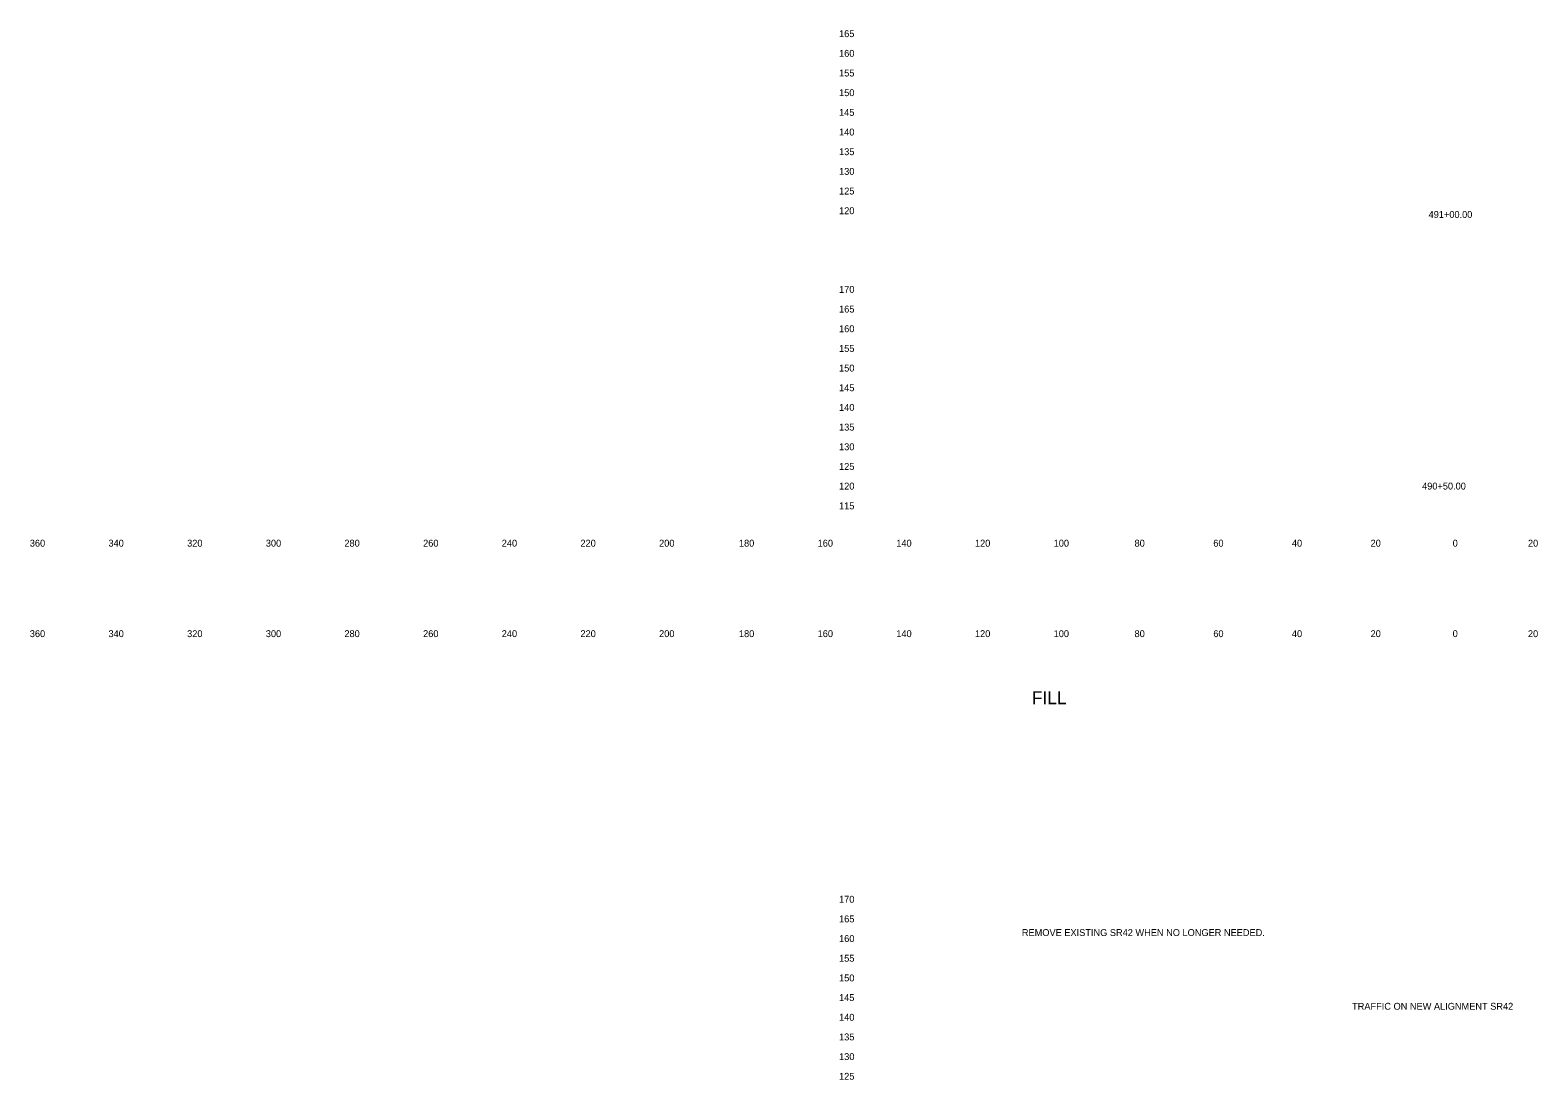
# Model space of a CAD drawing. Extents: x 21281 to 22024, y 6472 to 15208.
# Drawn here: x 21280.5 to 21663.8, y 14389.8 to 14656.6 of the extents above; entities that cross this region are included whole.
import ezdxf

# ---------------------------------------------------------------- set-up
doc = ezdxf.new("R2010")
doc.units = 0
for name, color, linetype in [('XS_SHEET_LABELS_ELEVATION', 7, 'Continuous'), ('XS_SHEET_LABELS_OFFSET', 7, 'Continuous'), ('XS_SHEET_LABELS_STATION', 7, 'Continuous')]:
    doc.layers.add(name, color=color, linetype=linetype)

msp = doc.modelspace()

# ---------------------------------------------------------------- texts
at = {"layer": 'XS_SHEET_LABELS_ELEVATION'}
for s, p in [('  165  ', (21484.84, 14654.84)), ('  160  ', (21484.84, 14649.84)), ('  155  ', (21484.84, 14644.84)), ('  150  ', (21484.84, 14639.84)), ('  145  ', (21484.84, 14634.84)), ('  140  ', (21484.84, 14629.84)), ('  135  ', (21484.84, 14624.84)), ('  130  ', (21484.84, 14619.84)), ('  125  ', (21484.84, 14614.84)), ('  120  ', (21484.84, 14609.84)), ('  170  ', (21484.84, 14589.84)), ('  165  ', (21484.84, 14584.84)), ('  160  ', (21484.84, 14579.84)), ('  155  ', (21484.84, 14574.84)), ('  150  ', (21484.84, 14569.84)), ('  145  ', (21484.84, 14564.84)), ('  140  ', (21484.84, 14559.84)), ('  135  ', (21484.84, 14554.84)), ('  130  ', (21484.84, 14549.84)), ('  125  ', (21484.84, 14544.84)), ('  120  ', (21484.84, 14539.84)), ('  115  ', (21484.84, 14534.84)), ('  170  ', (21484.84, 14434.84)), ('  165  ', (21484.84, 14429.84)), ('  160  ', (21484.84, 14424.84)), ('  155  ', (21484.84, 14419.84)), ('  150  ', (21484.84, 14414.84)), ('  145  ', (21484.84, 14409.84)), ('  140  ', (21484.84, 14404.84)), ('  135  ', (21484.84, 14399.84)), ('  130  ', (21484.84, 14394.84)), ('  125  ', (21484.84, 14389.84))]:
    msp.add_text(s, height=1.75, dxfattribs=at).set_placement(p)
at = {"layer": 'XS_SHEET_LABELS_OFFSET'}
for s, height, p in [('  360  ', 1.75, (21279.14, 14525.34)), ('  340  ', 1.75, (21299.13, 14525.34)), ('  320  ', 1.75, (21319.13, 14525.34)), ('  300  ', 1.75, (21339.13, 14525.34)), ('  280  ', 1.75, (21359.1, 14525.34)), ('  260  ', 1.75, (21379.11, 14525.34)), ('  240  ', 1.75, (21399.1, 14525.34)), ('  220  ', 1.75, (21419.1, 14525.34)), ('  200  ', 1.75, (21439.1, 14525.34)), ('  180  ', 1.75, (21459.39, 14525.34)), ('  160  ', 1.75, (21479.4, 14525.34)), ('  140  ', 1.75, (21499.39, 14525.34)), ('  120  ', 1.75, (21519.39, 14525.34)), ('  100  ', 1.75, (21539.39, 14525.34)), ('  80  ', 1.75, (21559.95, 14525.34)), ('  60  ', 1.75, (21579.97, 14525.34)), ('  40  ', 1.75, (21599.95, 14525.34)), ('  20  ', 1.75, (21619.95, 14525.34)), ('  0  ', 1.75, (21640.81, 14525.34)), ('  0  ', 1.75, (21640.81, 14525.34)), ('  20  ', 1.75, (21659.95, 14525.34)), ('  360  ', 1.75, (21279.14, 14502.34)), ('  340  ', 1.75, (21299.13, 14502.34)), ('  320  ', 1.75, (21319.13, 14502.34)), ('  300  ', 1.75, (21339.13, 14502.34)), ('  280  ', 1.75, (21359.1, 14502.34)), ('  260  ', 1.75, (21379.11, 14502.34)), ('  240  ', 1.75, (21399.1, 14502.34)), ('  220  ', 1.75, (21419.1, 14502.34)), ('  200  ', 1.75, (21439.1, 14502.34)), ('  180  ', 1.75, (21459.39, 14502.34)), ('  160  ', 1.75, (21479.4, 14502.34)), ('  140  ', 1.75, (21499.39, 14502.34)), ('  120  ', 1.75, (21519.39, 14502.34)), ('  100  ', 1.75, (21539.39, 14502.34)), ('  80  ', 1.75, (21559.95, 14502.34)), ('  60  ', 1.75, (21579.97, 14502.34)), ('  40  ', 1.75, (21599.95, 14502.34)), ('  20  ', 1.75, (21619.95, 14502.34)), ('  0  ', 1.75, (21640.81, 14502.34)), ('  0  ', 1.75, (21640.81, 14502.34)), ('  20  ', 1.75, (21659.95, 14502.34)), ('FILL', 3.273, (21535.18, 14485.29))]:
    msp.add_text(s, height=height, dxfattribs=at).set_placement(p)
at = {"layer": 'XS_SHEET_LABELS_STATION'}
for s, p in [('  491+00.00  ', (21634.69, 14608.89)), ('  490+50.00  ', (21633.04, 14539.85)), ('REMOVE EXISTING SR42 WHEN NO LONGER NEEDED.', (21532.61, 14426.37)), ('TRAFFIC ON NEW ALIGNMENT SR42', (21616.55, 14407.63))]:
    msp.add_text(s, height=1.75, dxfattribs=at).set_placement(p)

doc.saveas('drawing.dxf')
